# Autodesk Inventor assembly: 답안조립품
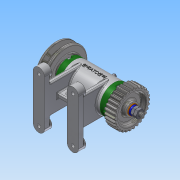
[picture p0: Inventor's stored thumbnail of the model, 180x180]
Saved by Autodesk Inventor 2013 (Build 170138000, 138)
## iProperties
Created: 2015-11
Part Number: 답안조립품
Document SubType Name: Assembly
Designer: Administrator
Author: Administrator
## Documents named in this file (16)
- C:\Users\Administrator\Desktop\451110V1048\답안조립품.iam
- C:\Users\Administrator\Desktop\451110V1048\본체.ipt
- C:\Users\Administrator\Desktop\451110V1048\V벨트풀리.ipt
- C:\Users\Administrator\Desktop\451110V1048\너트 M 8.ipt
- C:\Users\Administrator\Desktop\451110V1048\니플 M 6 x 0.75.ipt
- C:\Users\Administrator\Desktop\451110V1048\베어링 15 x 32 x 9.ipt
- C:\Users\Administrator\Desktop\451110V1048\볼트 M 6 x 8.ipt
- C:\Users\Administrator\Desktop\451110V1048\볼트 M4 x 12.ipt
- C:\Users\Administrator\Desktop\451110V1048\스퍼기어.ipt
- C:\Users\Administrator\Desktop\451110V1048\스프링와셔 8.ipt
- C:\Users\Administrator\Desktop\451110V1048\오일 실 15 25 7.ipt
- C:\Users\Administrator\Desktop\451110V1048\와셔 6x11.5.ipt
- C:\Users\Administrator\Desktop\451110V1048\와셔 8x17.ipt
- C:\Users\Administrator\Desktop\451110V1048\축.ipt
- C:\Users\Administrator\Desktop\451110V1048\커버.ipt
- C:\Users\Administrator\Desktop\451110V1048\키 3 x 3 x 12.ipt
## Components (11 placed, 3 different names)
1. V벨트풀리:1
2. KS B 2023 6002 - 15 x 32 x 9:1
3. KS B 2023 6002 - 15 x 32 x 9:2
4. ISO 4762 M4 x 12:2
5. ISO 4762 M4 x 12:3
6. ISO 4762 M4 x 12:4
7. ISO 4762 M4 x 12:5
8. ISO 4762 M4 x 12:1
9. ISO 4762 M4 x 12:6
10. ISO 4762 M4 x 12:7
11. ISO 4762 M4 x 12:8
